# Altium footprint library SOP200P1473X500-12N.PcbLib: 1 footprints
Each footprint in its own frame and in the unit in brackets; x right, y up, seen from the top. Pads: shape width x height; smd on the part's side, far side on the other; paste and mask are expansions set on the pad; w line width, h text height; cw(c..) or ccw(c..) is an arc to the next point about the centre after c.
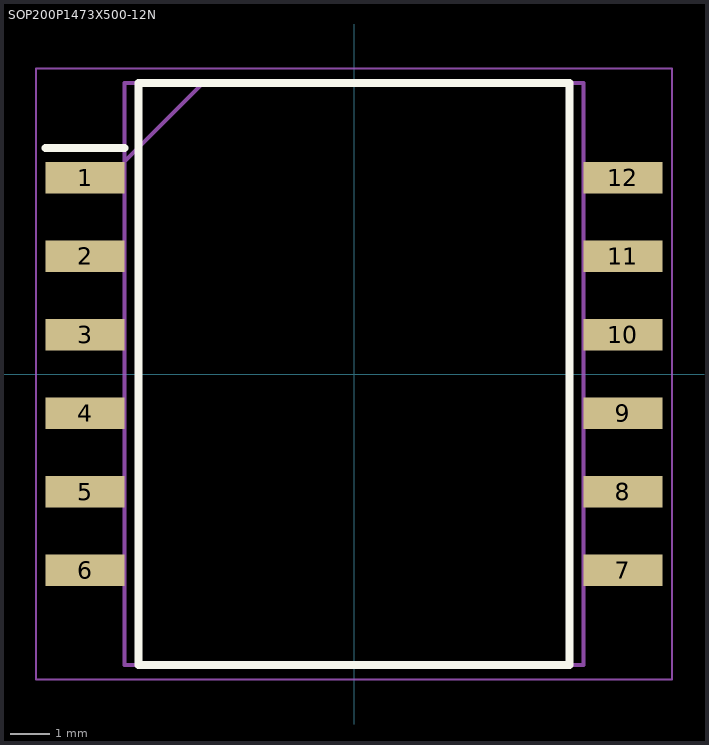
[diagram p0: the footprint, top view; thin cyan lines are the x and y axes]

## SOP200P1473X500-12N [mm]
pads (12):
  rect 2.01x0.8 smd: 1(-6.845,5) 2(-6.845,3) 3(-6.845,1) 4(-6.845,-1) 5(-6.845,-3) 6(-6.845,-5) 7(6.845,-5) 8(6.845,-3) 9(6.845,-1) 10(6.845,1) 11(6.845,3) 12(6.845,5)
Top Overlay:
  lines w0.2: -7.85,5.75 -5.84,5.75 ; -5.49,-7.405 5.49,-7.405 5.49,7.405 -5.49,7.405 -5.49,-7.405
Mechanical 15:
  lines w0.1: -5.84,5.405 -3.84,7.405 ; -5.84,-7.405 5.84,-7.405 5.84,7.405 -5.84,7.405 -5.84,-7.405
Mechanical 20:
  lines w0.05: -8.1,-7.78 8.1,-7.78 8.1,7.78 -8.1,7.78 -8.1,-7.78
